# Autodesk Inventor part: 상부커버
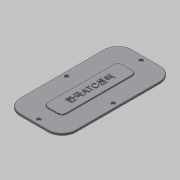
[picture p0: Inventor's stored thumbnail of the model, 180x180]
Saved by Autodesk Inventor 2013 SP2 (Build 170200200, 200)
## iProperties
Created: 2016-02
Part Number: 상부커버
Material: 일반
Document SubType Name: Modeling
Designer: mduedu
Density: 1 g/cm^3
Mass: 15.5198 g
Surface Area: 149.263 cm^2
Volume: 15.5198 cm^3
Author: mduedu
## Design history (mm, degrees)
sketch "스케치1"
  geometry: L1 (30, 60)-(-30, 60); L2 (-30, 60)-(-30, -60); L3 (-30, -60)-(30, -60); L4 (30, -60)-(30, 60); L5 (30, 60)-(-30, -60); L6 (-30, 60)-(30, -60); 1 further point
  constraints: 12 end point, 2 midpoint, 2 parallel, 1 horizontal, 1 perpendicular
  dimensions: "d0" = 60 distance of L2.end L3.end; "d2" = 120 distance of L1.end L2.end
extrude "돌출1" new body sketch "스케치1" distance "d3" = 2; taper "d4" = 0 deg
fillet "모깎기1" dims "d5" = 15
sketch "스케치2"
  geometry: L1 (30, 45)-(30, -45) reference; L2 (15, -60)-(-15, -60) reference; L3 (-30, -45)-(-30, 45) reference; L4 (-15, 60)-(15, 60) reference; L5 (25, 45)-(25, -45); L6 (15, -55)-(-15, -55); L7 (-25, -45)-(-25, 45); L8 (-15, 55)-(15, 55); A1 r 15 centre (15, 45) between (30, 45) and (15, 60) reference; A2 r 15 centre (15, -45) between (15, -60) and (30, -45) reference; A3 r 15 centre (-15, -45) between (-30, -45) and (-15, -60) reference; A4 r 15 centre (-15, 45) between (-15, 60) and (-30, 45) reference; A5 r 10 centre (15, 45) between (25, 45) and (15, 55); A6 r 10 centre (15, -45) between (15, -55) and (25, -45); A7 r 10 centre (-15, -45) between (-25, -45) and (-15, -55); A8 r 10 centre (-15, 45) between (-15, 55) and (-25, 45); 4 further points
  constraints: 8 end point, 8 point on circle, 4 centre point, 4 midpoint, 7 other
  dimensions: "d8" = 5 distance between parallel lines of L7 L3
hole "구멍1" sketch "스케치2" at (0, 55), (25, 0), (0, -55), (-25, 0) diameter "d9" = 4; stored, may be unused: countersink angle "d13" = 90 deg, drill point angle "d15" = 118 deg; dims "d10" = 6, "d11" = 4, "d12" = 2, "d14" = 8
sketch "스케치3"
  geometry: L1 (10, -40)-(-10, -40); L2 (-10, -40)-(-10, 40); L3 (-10, 40)-(10, 40); L4 (10, 40)-(10, -40); L5 (10, -40)-(-10, 40); L6 (-10, -40)-(10, 40); 1 further point
  constraints: 12 end point, 2 midpoint, 2 parallel, 1 horizontal, 1 perpendicular
  dimensions: "d16" = 80 distance of L1.end L2.end; "d18" = 20 distance of L2.end L3.end
extrude "돌출2" join sketch "스케치3" distance "d19" = 1; taper "d20" = 0 deg
fillet "모깎기2" dims "d21" = 5
fillet "모깎기3" dims "d22" = 0.3
fillet "모깎기4" dims "d23" = 0.3
sketch "스케치4"
  geometry: 2 further points
  constraints: 1 coincident, 1 other
feature "엠보싱1" sketch "스케치4" dims "d0" = 60, "d2" = 120, "d8" = 5, "d24" = 0.5, "d25" = 0
node "솔리드1"
node "절단 모서리 투영1"
